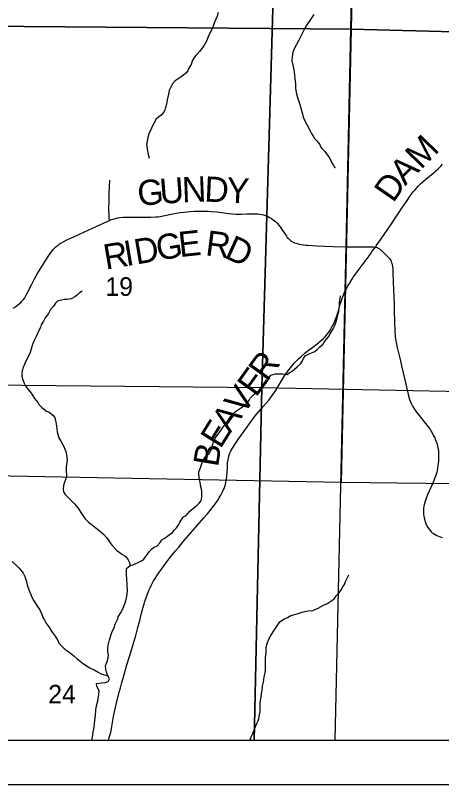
# Model space of a CAD drawing. Extents: x -19.9 to 41.9, y 0 to 32.3.
# Drawn here: x 6.268 to 7.228, y 14 to 15.733 of the extents above; entities that cross this region are included whole.
import ezdxf

# ---------------------------------------------------------------- set-up
doc = ezdxf.new("R2010")
doc.units = 0
for name, color, linetype in [('GM_X_Corporation', 7, 'Continuous'), ('GM_X_County_Road', 7, 'Continuous'), ('GM_X_County_Road_Text', 7, 'Continuous'), ('GM_X_Minor_River', 7, 'Continuous'), ('GM_X_Section', 7, 'Continuous'), ('GM_X_Section_Text', 7, 'Continuous'), ('GM_X_Township', 7, 'Continuous'), ('GM_X_Township_Road', 7, 'Continuous'), ('SH_Data', 7, 'Continuous')]:
    doc.layers.add(name, color=color, linetype=linetype)

msp = doc.modelspace()

# ---------------------------------------------------------------- linework, layer by layer
at = {"layer": 'GM_X_Corporation'}
for points in [[(2.1, 17.918), (2.1, 14.1), (8.9, 14.1), (8.9, 17.8974), (7.9072, 17.9171), (7.5529, 17.9242), (7.3858, 17.9277), (6.9468, 17.937), (6.7, 17.9422), (6.3069, 17.9505), (6.2497, 17.9517), (6.2397, 17.9517), (5.9048, 17.9534), (5.761, 17.9543), (5.4954, 17.9559), (5.0257, 17.9637), (5.0192, 17.8403), (4.9169, 17.8392), (4.2613, 17.8672), (3.984, 17.879), (3.7505, 17.884), (2.973, 17.9007), (2.4715, 17.9106)], [(6.8522, 15.9041), (6.8226, 14.894), (5.8188, 14.9036), (5.8404, 15.9209)], [(7.8659, 15.8953), (7.8436, 14.8739), (6.8226, 14.894), (6.8522, 15.9041)], [(5.7974, 14.1), (6.8053, 14.1), (6.8226, 14.894), (5.8188, 14.9036)], [(6.8053, 14.1), (7.8255, 14.1), (7.8436, 14.8739), (6.8226, 14.894)]]:
    msp.add_lwpolyline(points, close=True, dxfattribs=at)
msp.add_lwpolyline([(2.1, 17.918), (2.1, 14.1), (7.8246, 14.1), (7.8518, 15.3043), (7.854, 15.4058), (7.8702, 16.1679), (7.8776, 16.5173), (7.9012, 17.4524), (7.9072, 17.9171)], dxfattribs=at)
at = {"layer": 'GM_X_County_Road'}
for points in [[(7.0786, 15.2109), (7.0805, 15.2137), (7.09, 15.2273), (7.1064, 15.2511), (7.115, 15.2634), (7.1236, 15.2762), (7.1385, 15.2987), (7.1487, 15.3138), (7.1573, 15.3262), (7.1641, 15.3352), (7.1675, 15.3396), (7.1726, 15.3454), (7.1756, 15.3487), (7.1807, 15.3537), (7.1864, 15.3587), (7.1925, 15.3638), (7.2009, 15.3706), (7.2117, 15.3797), (7.2151, 15.3827), (7.2202, 15.3875), (7.2262, 15.3936), (7.2302, 15.3981)], [(6.2625, 15.0731), (6.2678, 15.0766), (6.2728, 15.0804), (6.2768, 15.0836), (6.2796, 15.0862), (6.2821, 15.089), (6.2857, 15.0928), (6.2886, 15.097), (6.2913, 15.1015), (6.2934, 15.1055), (6.3049, 15.1277), (6.311, 15.1397), (6.3173, 15.1512), (6.3219, 15.1588), (6.3284, 15.1693), (6.3359, 15.1813), (6.3412, 15.1896), (6.3475, 15.1985), (6.3512, 15.2032), (6.3538, 15.2062), (6.3568, 15.2093), (6.3597, 15.2121), (6.3637, 15.2153), (6.3672, 15.218), (6.3715, 15.2207), (6.3765, 15.2236), (6.3838, 15.2274), (6.3907, 15.2306), (6.4026, 15.236), (6.4513, 15.2584), (6.4748, 15.2688), (6.4799, 15.271), (6.4845, 15.2729), (6.4883, 15.2743), (6.4933, 15.2757), (6.4979, 15.2767), (6.5033, 15.2774), (6.5102, 15.2782), (6.5185, 15.2786), (6.5229, 15.2787), (6.551, 15.2785), (6.5672, 15.2782), (6.573, 15.2784), (6.5841, 15.2789), (6.5894, 15.2794), (6.5947, 15.2801), (6.6004, 15.2811), (6.6261, 15.2865), (6.6392, 15.2887), (6.6472, 15.2898), (6.6548, 15.2906), (6.6622, 15.2913), (6.6701, 15.2917), (6.6774, 15.292), (6.6839, 15.2922), (6.6963, 15.292), (6.7023, 15.2919), (6.709, 15.2914), (6.7218, 15.2902), (6.7273, 15.2896), (6.7381, 15.288), (6.748, 15.2866), (6.7571, 15.2856), (6.764, 15.2852), (6.7692, 15.2851), (6.7772, 15.2852), (6.7888, 15.2857), (6.7965, 15.2859), (6.8096, 15.2858), (6.814, 15.2856), (6.8182, 15.285), (6.8228, 15.2844), (6.8268, 15.2834), (6.8304, 15.2823), (6.834, 15.2809), (6.837, 15.2796), (6.8405, 15.2778), (6.8443, 15.2756), (6.8484, 15.2727), (6.8535, 15.2686), (6.8567, 15.2657), (6.858, 15.2643), (6.8635, 15.2577), (6.866, 15.2543), (6.8698, 15.2485), (6.8744, 15.2417), (6.8781, 15.236), (6.8803, 15.233), (6.8827, 15.2304), (6.8851, 15.2281), (6.8877, 15.2259), (6.8908, 15.2238), (6.8938, 15.2221), (6.8965, 15.2208), (6.8993, 15.2198), (6.9049, 15.2183), (6.9105, 15.2171), (6.9161, 15.2162), (6.9221, 15.2155), (6.9257, 15.2153), (6.947, 15.2142), (6.9826, 15.2127), (7.0123, 15.2117), (7.0181, 15.2115)], [(7.0162, 15.1223), (7.0204, 15.1293), (7.0257, 15.1379), (7.0288, 15.1429), (7.034, 15.1503), (7.0384, 15.1563), (7.0445, 15.1645), (7.049, 15.1705), (7.054, 15.1771), (7.0574, 15.1817), (7.0614, 15.1872), (7.065, 15.192), (7.0682, 15.1966), (7.0717, 15.2015), (7.0759, 15.2071), (7.0786, 15.2109)], [(7.0181, 15.2115), (7.055, 15.2116), (7.0708, 15.2117), (7.0727, 15.2116), (7.0748, 15.2115), (7.0773, 15.2111), (7.0786, 15.2109), (7.0803, 15.2105), (7.0825, 15.2098), (7.0844, 15.209), (7.0861, 15.208), (7.0877, 15.2069), (7.0968, 15.1992), (7.0994, 15.1969), (7.1056, 15.1909), (7.1078, 15.1884), (7.1103, 15.1853), (7.1119, 15.1828), (7.1132, 15.1806), (7.1145, 15.1779), (7.1157, 15.1746), (7.1167, 15.171), (7.1172, 15.167), (7.1177, 15.1617), (7.1181, 15.1536), (7.119, 15.1326), (7.1198, 15.115), (7.1202, 15.0998), (7.1207, 15.08), (7.1212, 15.0632), (7.1217, 15.0474), (7.1221, 15.0364), (7.1224, 15.0269), (7.1226, 15.019), (7.1231, 15.0136), (7.1236, 15.0084), (7.125, 15.0001), (7.1281, 14.9849), (7.1315, 14.9696), (7.135, 14.9547), (7.1377, 14.9436), (7.1452, 14.9118), (7.1543, 14.8726), (7.1559, 14.8675), (7.1577, 14.8623), (7.1598, 14.8573), (7.1623, 14.8526), (7.1653, 14.8478), (7.169, 14.8424), (7.1751, 14.8346), (7.1885, 14.8177), (7.1973, 14.8063), (7.201, 14.8012), (7.2043, 14.7963), (7.2074, 14.791), (7.21, 14.786), (7.2123, 14.7811), (7.2135, 14.7784), (7.2168, 14.7694), (7.2178, 14.7661), (7.2196, 14.7592), (7.2203, 14.7558), (7.2207, 14.7522), (7.2211, 14.7472), (7.221, 14.7352), (7.2206, 14.7278), (7.2197, 14.7199), (7.2184, 14.7122), (7.2168, 14.7043), (7.2146, 14.6969), (7.212, 14.6888), (7.2079, 14.6794), (7.1998, 14.6614), (7.1954, 14.6512), (7.1929, 14.6445), (7.1916, 14.6405), (7.1887, 14.6304), (7.1881, 14.6274), (7.1874, 14.6227), (7.1871, 14.6184), (7.1869, 14.6138), (7.187, 14.6094), (7.1876, 14.605), (7.1883, 14.6009), (7.1891, 14.5978), (7.1905, 14.5929), (7.1919, 14.589), (7.1936, 14.5851), (7.1955, 14.5815), (7.197, 14.579), (7.1995, 14.5755), (7.2019, 14.5724), (7.2045, 14.5696), (7.207, 14.5675), (7.2095, 14.5656), (7.2131, 14.5635), (7.2171, 14.5613), (7.221, 14.5595), (7.2248, 14.5581), (7.2288, 14.557)], [(6.8506, 14.8828), (6.8534, 14.8872), (6.8715, 14.917), (6.874, 14.9208), (6.8815, 14.9315), (6.8841, 14.9349), (6.8934, 14.9464), (6.8961, 14.9495), (6.9008, 14.9544), (6.9055, 14.9591), (6.9113, 14.9646), (6.9182, 14.9707), (6.9207, 14.9728), (6.9274, 14.9778), (6.9348, 14.9835), (6.9505, 14.9952), (6.9538, 14.998), (6.9617, 15.0051), (6.9642, 15.0077), (6.9688, 15.0129), (6.9709, 15.0154), (6.9735, 15.0191), (6.9765, 15.0233), (6.9779, 15.0256), (6.9802, 15.0296), (6.983, 15.0349), (6.9863, 15.0418), (6.9892, 15.0487), (6.991, 15.0538), (6.9933, 15.0605), (6.9953, 15.0671), (6.9979, 15.0761), (6.9997, 15.0821), (7.0017, 15.0885), (7.0039, 15.0952), (7.006, 15.1012), (7.0073, 15.1047), (7.0087, 15.1079), (7.0113, 15.1131), (7.0141, 15.1182), (7.0162, 15.1223)], [(6.4775, 14.1), (6.4793, 14.1059), (6.4812, 14.1126), (6.4827, 14.1184), (6.4834, 14.1215), (6.485, 14.131), (6.4862, 14.1396), (6.4886, 14.1533), (6.4894, 14.1575), (6.4929, 14.1735), (6.4947, 14.181), (6.5024, 14.2107), (6.5046, 14.2184), (6.5078, 14.2301), (6.5105, 14.2402), (6.519, 14.2697), (6.5246, 14.2883), (6.5346, 14.3213), (6.5388, 14.3363), (6.5437, 14.3543), (6.5477, 14.3698), (6.5521, 14.3866), (6.5556, 14.3997), (6.5575, 14.4063), (6.5587, 14.4107), (6.5606, 14.4167), (6.5622, 14.4211), (6.5646, 14.4278), (6.566, 14.4314), (6.5684, 14.4373), (6.5714, 14.4437), (6.5739, 14.4488), (6.5792, 14.4588), (6.5825, 14.4644), (6.5864, 14.4706), (6.5909, 14.477), (6.5969, 14.4855), (6.6091, 14.502), (6.6157, 14.5106), (6.6217, 14.5184), (6.6284, 14.5266), (6.6359, 14.5353), (6.6415, 14.5419), (6.6475, 14.5489), (6.6735, 14.5791), (6.6872, 14.5949), (6.6925, 14.6012), (6.7003, 14.6104), (6.7086, 14.6203), (6.7111, 14.6235), (6.7156, 14.6292), (6.72, 14.6356), (6.7228, 14.6397), (6.727, 14.6464), (6.7311, 14.6535), (6.7335, 14.6581), (6.7367, 14.6647), (6.7377, 14.6672), (6.7394, 14.6717), (6.7407, 14.6762), (6.7421, 14.6816), (6.7432, 14.6876), (6.7442, 14.6948), (6.7449, 14.7023), (6.7454, 14.7119), (6.7456, 14.7189), (6.7459, 14.7263), (6.7461, 14.7277), (6.7468, 14.7328), (6.7482, 14.7389), (6.7486, 14.7403), (6.7501, 14.745), (6.7522, 14.7501), (6.7531, 14.752), (6.7551, 14.7557), (6.7581, 14.7606), (6.7636, 14.7689), (6.771, 14.7796), (6.7941, 14.8119), (6.8022, 14.8229), (6.8078, 14.8305), (6.8124, 14.8361), (6.8214, 14.8465), (6.8328, 14.8595), (6.8384, 14.8663), (6.8423, 14.8715), (6.85, 14.882), (6.8506, 14.8828)]]:
    msp.add_lwpolyline(points, dxfattribs=at)
at = {"layer": 'GM_X_Minor_River'}
msp.add_line((7.0156, 14.4667), (7.0189, 14.4725), dxfattribs=at)
for points in [[(6.7248, 15.7397), (6.7219, 15.7313), (6.7164, 15.7179), (6.7117, 15.7041), (6.7058, 15.6933), (6.7017, 15.6849), (6.6985, 15.675), (6.6925, 15.6646), (6.6825, 15.6519), (6.6751, 15.6438)], [(6.9399, 15.7353), (6.9314, 15.7219), (6.9243, 15.7119), (6.9202, 15.7057), (6.9166, 15.6984), (6.9114, 15.6881), (6.9059, 15.6773), (6.9011, 15.6678), (6.8956, 15.6574), (6.893, 15.6501), (6.8909, 15.6398), (6.8907, 15.6307), (6.8927, 15.6212), (6.8943, 15.6144), (6.896, 15.606), (6.8968, 15.5984), (6.8973, 15.5912), (6.8982, 15.5844), (6.8986, 15.5786), (6.8991, 15.5688), (6.9004, 15.5593), (6.9032, 15.5479), (6.9084, 15.5324), (6.9124, 15.5187), (6.9164, 15.502), (6.9203, 15.4937), (6.925, 15.4854), (6.9308, 15.4745), (6.9347, 15.4673), (6.9386, 15.4609), (6.9417, 15.4556), (6.9467, 15.4507), (6.9532, 15.4425), (6.9552, 15.4372), (6.9587, 15.4323), (6.9645, 15.4263), (6.9687, 15.421), (6.9726, 15.4161), (6.976, 15.4108), (6.9807, 15.401), (6.9842, 15.395), (6.987, 15.3893), (6.9878, 15.3919)], [(6.6751, 15.6438), (6.6706, 15.638), (6.6654, 15.6288), (6.6644, 15.6238), (6.6585, 15.6138), (6.6563, 15.6085), (6.6514, 15.6031), (6.6462, 15.5984), (6.6413, 15.5949), (6.6342, 15.5899), (6.6278, 15.5856), (6.6215, 15.579), (6.6171, 15.5702), (6.6141, 15.5641), (6.6124, 15.5553), (6.6095, 15.5431), (6.6078, 15.5327), (6.606, 15.5255), (6.6045, 15.5198), (6.6016, 15.5144), (6.5964, 15.5086), (6.5908, 15.5047), (6.5852, 15.4989), (6.5804, 15.4912), (6.5756, 15.4824), (6.5726, 15.4751), (6.5689, 15.4682), (6.5675, 15.4632), (6.5654, 15.4548), (6.5643, 15.448), (6.5633, 15.4426), (6.5642, 15.4324), (6.5658, 15.4232), (6.5674, 15.4164), (6.569, 15.4111), (6.5694, 15.4119)], [(6.4178, 15.1116), (6.4122, 15.108), (6.4069, 15.1026), (6.4017, 15.0988), (6.393, 15.0941), (6.384, 15.0928), (6.3772, 15.0927), (6.3689, 15.091), (6.3628, 15.089), (6.358, 15.0844), (6.3535, 15.0782), (6.3468, 15.0701), (6.342, 15.0617), (6.3346, 15.0513), (6.3309, 15.044), (6.3261, 15.036), (6.3239, 15.0298), (6.321, 15.0245), (6.3181, 15.0176), (6.3144, 15.0099), (6.31, 15.0003), (6.3063, 14.9919), (6.3038, 14.9838), (6.3013, 14.9739), (6.2961, 14.9639), (6.2928, 14.957), (6.2892, 14.9486), (6.2855, 14.9398), (6.283, 14.9322), (6.2819, 14.926), (6.2824, 14.9203), (6.2844, 14.912), (6.2875, 14.9041), (6.291, 14.8973), (6.2964, 14.8905), (6.3007, 14.8852), (6.3046, 14.8796), (6.3104, 14.8698), (6.3181, 14.8611), (6.3212, 14.8558), (6.3273, 14.8498), (6.338, 14.8412), (6.3441, 14.8391), (6.3518, 14.8327), (6.3568, 14.8271), (6.3584, 14.8199), (6.3597, 14.8134), (6.3601, 14.8069), (6.3618, 14.7948), (6.363, 14.7899), (6.3654, 14.7815), (6.3697, 14.774), (6.374, 14.7668), (6.3767, 14.7615), (6.3787, 14.7555), (6.381, 14.7505), (6.3835, 14.7392), (6.384, 14.7304), (6.3829, 14.722), (6.3823, 14.7155), (6.3824, 14.706), (6.3829, 14.6992), (6.3826, 14.6931), (6.3808, 14.6877), (6.3782, 14.6812), (6.3757, 14.674), (6.3751, 14.6656), (6.3759, 14.6599), (6.3798, 14.6538), (6.3898, 14.6437), (6.4009, 14.6329), (6.4082, 14.6235), (6.4183, 14.6088), (6.421, 14.6038), (6.4257, 14.5978), (6.4322, 14.5911), (6.4417, 14.5844), (6.449, 14.5784), (6.4563, 14.5728), (6.4613, 14.5679), (6.4667, 14.5638), (6.4732, 14.5567), (6.4767, 14.5514), (6.4809, 14.545), (6.4856, 14.5386), (6.4956, 14.5281), (6.5006, 14.5244), (6.509, 14.5188), (6.5139, 14.5151), (6.5189, 14.5117), (6.5216, 14.5068), (6.524, 14.5019), (6.5266, 14.4937)], [(6.6844, 14.714), (6.6895, 14.7278), (6.694, 14.7355), (6.6988, 14.742), (6.7044, 14.7463), (6.7085, 14.754), (6.7124, 14.7666), (6.7139, 14.772), (6.7179, 14.7804), (6.7239, 14.7885), (6.7291, 14.7954), (6.735, 14.8042), (6.7409, 14.8123), (6.7458, 14.8189), (6.7495, 14.825), (6.7535, 14.8304), (6.7588, 14.8358), (6.7632, 14.8408), (6.7681, 14.8436), (6.7752, 14.8479), (6.7827, 14.8533), (6.7906, 14.861), (6.7943, 14.866), (6.7969, 14.871), (6.804, 14.8784), (6.8096, 14.8826), (6.8144, 14.8865), (6.8208, 14.8912), (6.8268, 14.8985), (6.8327, 14.9047), (6.8357, 14.9105), (6.8394, 14.917), (6.8434, 14.9224), (6.854, 14.9252), (6.8608, 14.9257), (6.8684, 14.9258), (6.8748, 14.9251), (6.8798, 14.9241), (6.8846, 14.9279), (6.891, 14.9318), (6.9026, 14.9412), (6.9097, 14.9481), (6.9145, 14.955), (6.9171, 14.96), (6.9208, 14.9662), (6.931, 14.9713), (6.9422, 14.9756), (6.9475, 14.9803), (6.9535, 14.9861), (6.9602, 14.9915), (6.9639, 14.9977), (6.9683, 15.0034), (6.9728, 15.0088), (6.9765, 15.0154), (6.9835, 15.0265), (6.9865, 15.0326), (6.9887, 15.0388), (6.9912, 15.0449), (6.9944, 15.0586), (6.9962, 15.0667), (6.9969, 15.0728), (6.9975, 15.0796), (6.9982, 15.0869), (6.9992, 15.0945), (6.9999, 15.101)], [(6.4397, 14.1), (6.4411, 14.1067), (6.4432, 14.1185), (6.445, 14.1288), (6.4456, 14.1365), (6.4466, 14.1452), (6.448, 14.1555), (6.449, 14.1681), (6.4507, 14.1776), (6.4532, 14.1891), (6.4556, 14.2028), (6.4563, 14.2112), (6.4532, 14.2169), (6.4512, 14.2226), (6.4504, 14.2279), (6.4617, 14.2292), (6.4704, 14.2301), (6.4768, 14.2325), (6.4797, 14.2382), (6.4762, 14.2454), (6.4731, 14.253), (6.4715, 14.2602), (6.471, 14.2678), (6.4728, 14.2739), (6.475, 14.2792), (6.4768, 14.2854), (6.4774, 14.2926), (6.4762, 14.2983), (6.4761, 14.307), (6.4767, 14.3143), (6.48, 14.3265), (6.4847, 14.3426), (6.4909, 14.3552), (6.4916, 14.3602), (6.4986, 14.3732), (6.4993, 14.3782), (6.5059, 14.3886), (6.5118, 14.4016), (6.5162, 14.4142), (6.5187, 14.4242), (6.5193, 14.4299), (6.52, 14.4364), (6.5198, 14.4497), (6.5188, 14.4641), (6.5183, 14.4729), (6.5181, 14.4869), (6.526, 14.4935), (6.532, 14.4955), (6.5373, 14.4975), (6.5444, 14.5007), (6.552, 14.5042), (6.5572, 14.5077), (6.5609, 14.5135), (6.5654, 14.5193), (6.5691, 14.5246), (6.5747, 14.5312), (6.5807, 14.5351), (6.5874, 14.5379), (6.5941, 14.5452), (6.5975, 14.5513), (6.6027, 14.5548), (6.6076, 14.5572), (6.614, 14.563), (6.6214, 14.5681), (6.6259, 14.5742), (6.6308, 14.5789), (6.636, 14.5858), (6.6385, 14.5912), (6.6467, 14.6031), (6.6523, 14.6062), (6.6609, 14.6159), (6.6699, 14.6236), (6.6766, 14.629), (6.6814, 14.6344), (6.6859, 14.6395), (6.6877, 14.6479), (6.6879, 14.6604), (6.687, 14.6654), (6.6858, 14.671), (6.6846, 14.676), (6.6833, 14.6851), (6.6817, 14.6923), (6.6809, 14.6988), (6.6812, 14.7049), (6.6844, 14.714)], [(6.2605, 14.5025), (6.27, 14.4939), (6.2754, 14.4882), (6.2797, 14.483), (6.2851, 14.4766), (6.2893, 14.4686), (6.2917, 14.4599), (6.2945, 14.4501), (6.2981, 14.4391), (6.3021, 14.4281), (6.3056, 14.4206), (6.3091, 14.4141), (6.3145, 14.4058), (6.3188, 14.3994), (6.3234, 14.3923), (6.3281, 14.3817), (6.3297, 14.3768), (6.3332, 14.3703), (6.3363, 14.3647), (6.3409, 14.3583), (6.3444, 14.353), (6.3494, 14.3459), (6.3529, 14.3406), (6.3572, 14.3342), (6.363, 14.3244), (6.3657, 14.3187), (6.3715, 14.3123), (6.3769, 14.3071), (6.3842, 14.3011), (6.3945, 14.294), (6.3999, 14.2895), (6.4068, 14.2835), (6.4137, 14.2783), (6.4213, 14.2723), (6.4293, 14.2668), (6.4351, 14.263), (6.4465, 14.2575), (6.4542, 14.2534), (6.4591, 14.2505), (6.4656, 14.2483), (6.4713, 14.2465), (6.4764, 14.2449)], [(6.5221, 14.5043), (6.522, 14.5045)], [(6.7961, 14.1), (6.7964, 14.1007), (6.7989, 14.1076), (6.8015, 14.1137), (6.8048, 14.1214), (6.8088, 14.1313), (6.8117, 14.1378), (6.8143, 14.1436), (6.8161, 14.1493), (6.8179, 14.157), (6.8189, 14.1642), (6.8195, 14.1741), (6.8194, 14.1836), (6.8201, 14.1905), (6.8211, 14.1973), (6.8225, 14.205), (6.8235, 14.2122), (6.8245, 14.2218), (6.8267, 14.2309), (6.8284, 14.2427), (6.8305, 14.2515), (6.8312, 14.2595), (6.8315, 14.2653), (6.8313, 14.2729), (6.8315, 14.2869), (6.8325, 14.2957), (6.8328, 14.3026), (6.8323, 14.3094), (6.8356, 14.3205), (6.8396, 14.3293), (6.8448, 14.3385), (6.8496, 14.3466), (6.8559, 14.3558), (6.8633, 14.367), (6.8734, 14.3736), (6.8809, 14.3768), (6.8885, 14.3807), (6.9024, 14.3851), (6.9141, 14.3883), (6.9201, 14.3903), (6.9269, 14.3912), (6.9375, 14.3921), (6.9496, 14.3972), (6.9631, 14.4047), (6.9691, 14.407), (6.9803, 14.4148), (6.9863, 14.4195), (6.9904, 14.4256), (6.9971, 14.4322), (7.0016, 14.4387), (7.0056, 14.4453), (7.009, 14.451), (7.0115, 14.4579), (7.0156, 14.4667)]]:
    msp.add_lwpolyline(points, dxfattribs=at)
at = {"layer": 'GM_X_Section'}
for points in [[(6.0276, 16.7357), (7.0463, 16.7153), (7.0239, 15.7019), (6.0103, 15.7106)], [(8.0651, 16.6907), (8.0435, 15.6754), (7.0239, 15.7019), (7.0463, 16.7153)], [(7.0239, 15.7019), (7.0016, 14.6805), (5.9806, 14.7005), (6.0103, 15.7106)], [(8.0435, 15.6754), (8.0175, 14.6683), (7.0016, 14.6805), (7.0239, 15.7019)]]:
    msp.add_lwpolyline(points, close=True, dxfattribs=at)
at = {"layer": 'GM_X_Township'}
for p, q in [((7.0282, 15.9744), (7.012, 15.2123)), ((7.012, 15.2123), (7.0099, 15.1108)), ((7.0099, 15.1108), (6.987, 14.1)), ((6.987, 14.1), (6.988, 14.1))]:
    msp.add_line(p, q, dxfattribs=at)
at = {"layer": 'GM_X_Township_Road'}
msp.add_lwpolyline([(6.4799, 15.271), (6.4792, 15.2768), (6.4786, 15.2837), (6.4784, 15.2935), (6.4788, 15.3189), (6.4792, 15.3335), (6.4802, 15.3616)], dxfattribs=at)
at = {"layer": 'SH_Data'}
for p, q in [((2.1, 14.1), (8.9, 14.1)), ((2, 14), (9, 14))]:
    msp.add_line(p, q, dxfattribs=at)

# ---------------------------------------------------------------- texts
at = {"layer": 'GM_X_County_Road_Text'}
for s, rotation, p in [('M', 46.0022, (7.1816, 15.3841)), ('A', 45.1442, (7.1456, 15.348)), ('D', 55.2834, (7.1189, 15.3089)), ('G', 4.6021, (6.5448, 15.3039)), ('U', 4.5546, (6.5947, 15.3079)), ('N', 2.2592, (6.6439, 15.3118)), ('D', 357.3872, (6.6926, 15.3138)), ('Y', 357.1392, (6.7425, 15.3115)), ('D', 9.6222, (6.5403, 15.1717)), ('G', 9.5815, (6.5896, 15.1801)), ('E', 6.2006, (6.638, 15.1883)), ('R', 352.6029, (6.6942, 15.1927)), ('D', 335.4343, (6.7361, 15.1879)), ('R', 9.6311, (6.4713, 15.16)), ('I', 9.6304, (6.5173, 15.1678)), ('R', 53.8108, (6.8345, 14.9056)), ('E', 54.3353, (6.8098, 14.8712)), ('V', 54.3374, (6.7806, 14.8306)), ('A', 54.395, (6.7515, 14.79)), ('E', 58.1182, (6.7296, 14.7547)), ('B', 80.6814, (6.7241, 14.7141))]:
    msp.add_text(s, height=0.0568, rotation=rotation, dxfattribs=at).set_placement(p)
at = {"layer": 'GM_X_Section_Text'}
for s, p in [('19', (6.4704, 15.1012)), ('24', (6.3417, 14.1828))]:
    msp.add_text(s, height=0.04186, rotation=0, dxfattribs=at).set_placement(p)

doc.saveas('drawing.dxf')
